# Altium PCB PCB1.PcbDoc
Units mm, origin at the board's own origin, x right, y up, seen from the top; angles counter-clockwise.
Board outline 40.13 x 100 mm, 2 copper layers (Top Layer, Bottom Layer); 44 components, 30 nets, 164 pads, 32 vias.
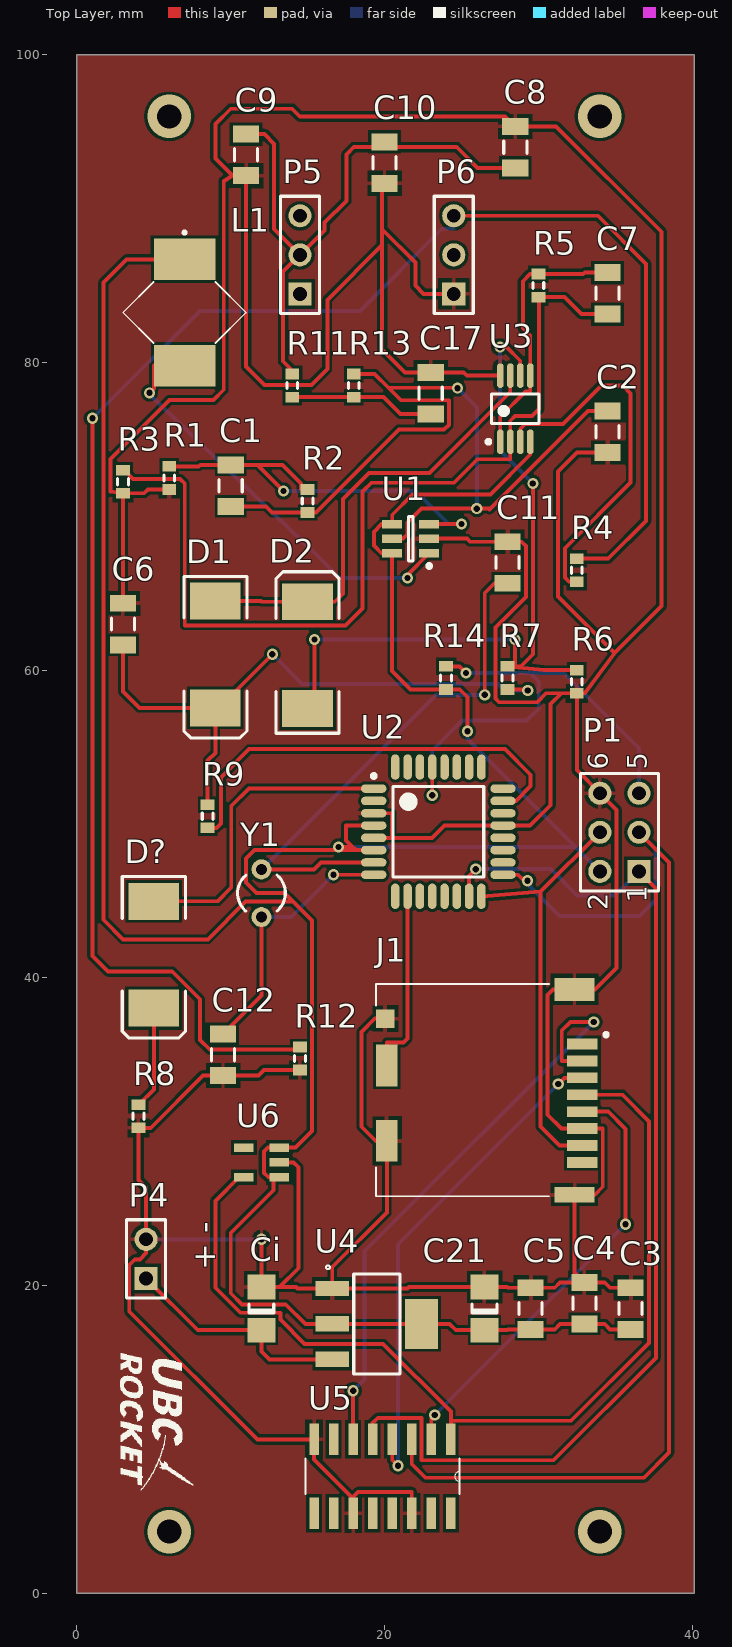
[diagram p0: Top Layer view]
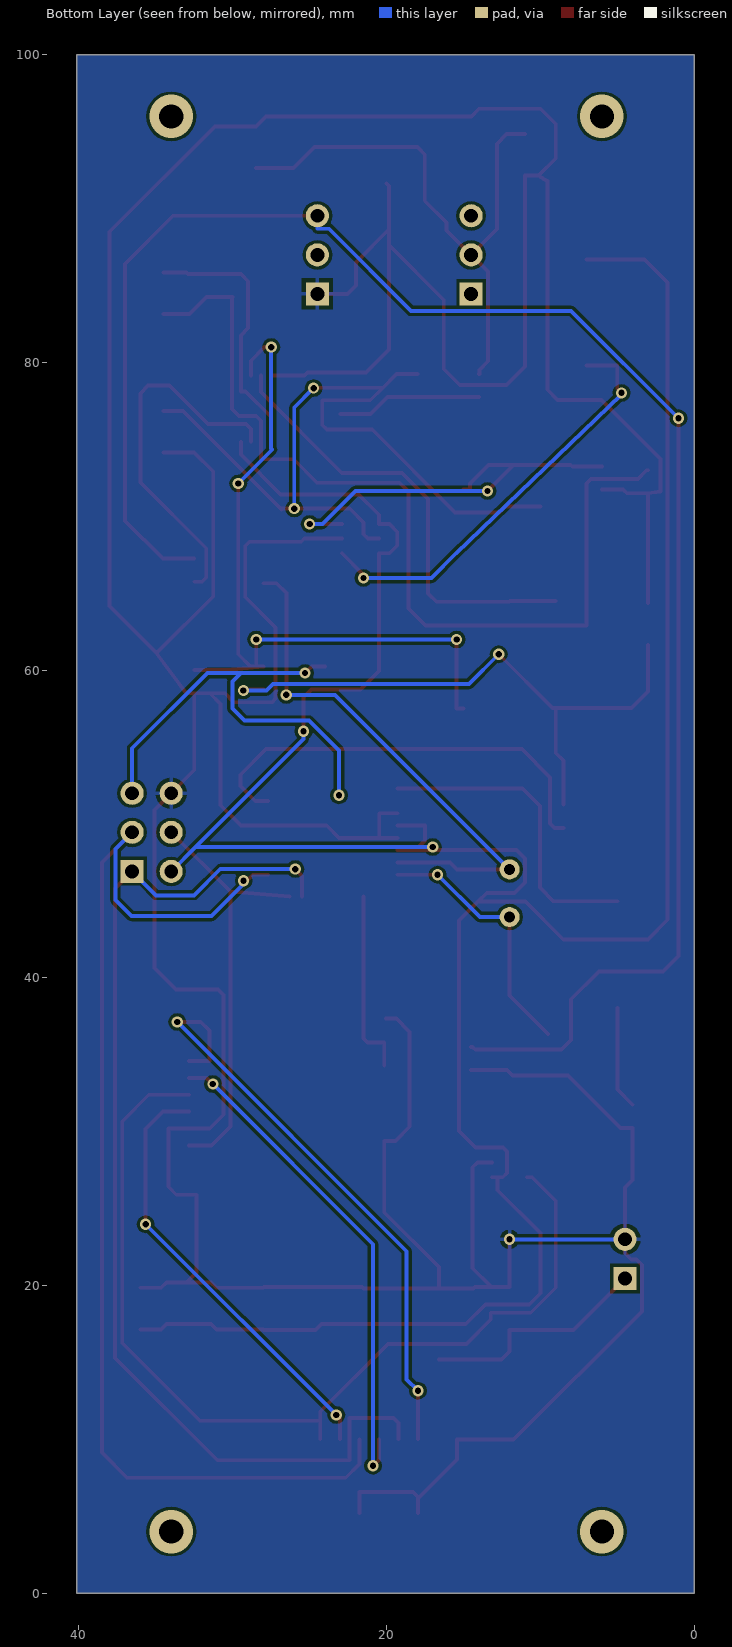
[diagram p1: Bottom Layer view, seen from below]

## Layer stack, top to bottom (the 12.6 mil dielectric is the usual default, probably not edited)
Top Solder: solder mask 0.0102, Solder Resist, Dk 3.5
Top Layer: signal copper 0.0356
Dielectric 1: dielectric 0.32, FR-4, Dk 4.8
Bottom Layer: signal copper 0.0356
Bottom Solder: solder mask 0.0102, Solder Resist, Dk 3.5

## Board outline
0,0 40.132,0 40.132,100 0,100

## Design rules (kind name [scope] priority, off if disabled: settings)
Clearance [All] p1: gap=0.2 ignorepadtopadclearanceinfootprint=FALSE
PolygonConnect [All] p1: connectstyle=Relief reliefconductorwidth=0.254 reliefentries=4 polygonreliefangle="90 Angle" airgapwidth=0.254
RoutingVias [All] p1: holewidth=0.406 width=0.725 viastyle="Through Hole" minholewidth=0.406 minwidth=0.725 maxholewidth=0.406 maxwidth=0.725
SolderMaskExpansion [All] p1: expansion=0.102
Width [All] p1: maxlimit=0.254 minlimit=0.254 preferedwidth=0.254
30 further rules are at their usual default settings.

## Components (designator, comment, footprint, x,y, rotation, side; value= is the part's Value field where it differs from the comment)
C1 "Cap Semi" C1206 10,72 r270 top value=22pF
C2 "Cap Semi" C1206 34.5,75.5 r90 top value=0.47uF
C3 "Cap Semi" C1206 36,18.5 r270 top value=1uF
C4 "Cap Semi" C1206 33,18.85 r270 top value=0.1uF
C5 "Cap Semi" C1206 29.5,18.5 r270 top value=10uF
C6 "Cap Semi" C1206 3,63 r270 top value=10nF
C7 "Cap Semi" C1206 34.5,84.5 r90 top value=5pF
C8 "Cap Semi" C1206 28.5,94 r270 top value=10nF
C9 "Cap Semi" C1206 11,93.5 r90 top value=10nF
C10 "Cap Semi" C1206 20,93 r90 top value=10nF
C11 "Cap Semi" C1206 28,67 r270 top value=22pF
C12 "Cap Semi" C1206 9.5,35 r90 top value=22pF
C17 "Cap Semi" C1206 23,78 r270 top value=10nF
C21 "47uF 6.3V" 1206 26.5,18.5 r90 top value=100pF
Ci "47uF 6.3V" 1206 12,18.5 r90 top value=100pF (schematic designator C?)
D1 "Diode" SMC 9,61.025 r270 top
D2 "Diode" SMC 15,60.975 r90 top
D? "Diode" SMC 5,41.5 r270 top
J1 "DM3CS-SF" HRS_DM3CS-SF_DM3CS-SF(Primary) 26.5,32.5 r90 top
L1 "CDR7D28MNNP-101NC" CDR7D28MNNP101NC 7,83.5 r270 top
P1 "ICSP Header" HDR2X3 36.54,46.92 r90 top
P4 "Header 2" HDR1X2 4.5,20.46 r90 top
P5 "Header 3" HDR1X3 14.5,84.46 r90 top
P6 "Header 3" HDR1X3 24.5,84.46 r90 top
R1 "Res3" J1-0603 6,72.5 r90 top value=10K
R2 "Res3" J1-0603 15,71 r270 top value=226K
R3 "Res3" J1-0603 3,72.25 r90 top value=500
R4 "Res3" J1-0603 32.5,66.5 r270 top value=1K
R5 "Res3" J1-0603 30,85 r90 top value=10K
R6 "Res3" J1-0603 32.5,59.25 r90 top value=100K
R7 "Res3" J1-0603 28,59.5 r90 top value=100K
R8 "Res3" J1-0603 4,31 r90 top value=1K
R9 "Res3" J1-0603 8.5,50.5 r270 top value=1K
R11 "Res3" J1-0603 14,78.5 r90 top value=49.9
R12 "Res3" J1-0603 14.5,34.75 r90 top value=49.9
R13 "Res3" J1-0603 18,78.5 r270 top value=49.9
R14 "Res3" J1-0603 24,59.5 r90 top value=10K
U1 "LT3461AES6" LT-S6-6-TSOT-23_N 21.7,68.55 r180 top
U2 "ATmega328P-15AZ" 32MA_N 23.5,49.5 r0 top
U3 "LT1807CMS8" LT-MS8-8_N 28.5,77 r90 top
U4 "NCP1117ST50T3G" SOT230P700X180-4N 19.5,17.5 r0 top
U5 "CD74HC4050M" SOIC127P600X175-16N 15.42,5.199 r270 top
U6 "LP2985IM5-3.3" SOT95P285X120-5N 12,28 r180 top
Y1 "XTAL" R38 12,45.5 r180 top

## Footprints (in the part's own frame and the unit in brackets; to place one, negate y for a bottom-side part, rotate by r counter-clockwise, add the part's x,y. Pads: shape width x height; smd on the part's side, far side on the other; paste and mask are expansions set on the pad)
32MA_N [mm] "Thin QFP, 32-Leads, Body 7x7mm, Pitch 0.8mm, IPC Medium Density"
  oval 1.65x0.55 smd: 1(-4.2,2.8) 2(-4.2,2) 3(-4.2,1.2) 4(-4.2,0.4) 5(-4.2,-0.4) 6(-4.2,-1.2) 7(-4.2,-2) 8(-4.2,-2.8) 17(4.2,-2.8) 18(4.2,-2) 19(4.2,-1.2) 20(4.2,-0.4) 21(4.2,0.4) 22(4.2,1.2) 23(4.2,2) 24(4.2,2.8)
  oval 0.55x1.65 smd: 9(-2.8,-4.2) 10(-2,-4.2) 11(-1.2,-4.2) 12(-0.4,-4.2) 13(0.4,-4.2) 14(1.2,-4.2) 15(2,-4.2) 16(2.8,-4.2) 25(2.8,4.2) 26(2,4.2) 27(1.2,4.2) 28(0.4,4.2) 29(-0.4,4.2) 30(-1.2,4.2) 31(-2,4.2) 32(-2.8,4.2)
  silkscreen extent -4.32,-2.95 2.95,3.75, body extent -3.5,-3.5 3.5,3.5, height 1.2
1206 [mm] "Chip Capacitor; Body 3.2 x 1.6 mm (LxW typ)"
  rect 1.6x1.8 smd: 1(-1.4,0) 2(1.4,0)
  silkscreen extent -0.3,-0.8 0.3,0.8
C1206 [mm] "Chip Capacitor, Body 3.2x1.6mm, IPC High Density"
  rect 1.1x1.7 smd: 1(-1.35,0) 2(1.35,0)
  silkscreen extent -0.4,-0.75 0.4,0.75, body extent -1.7,-0.9 1.7,0.9, height 1.3
CDR7D28MNNP101NC [mm]
  rect 2.7x4 smd: 1(-3.2,0) 2(3.7,0)
  silkscreen extent -5.05,-4 2.25,4
HDR1X2 [mm] "Connector; Header; 2 Position"
  rect 1.5x1.5 hole 0.9: 1(0,0)
  round 1.5 hole 0.9: 2(2.54,0)
  silkscreen extent -1.27,-1.27 3.81,1.27
HDR1X3 [mm] "Connector; Header; 3 Position"
  rect 1.5x1.5 hole 0.9: 1(0,0)
  round 1.5 hole 0.9: 2(2.54,0) 3(5.08,0)
  silkscreen extent -1.27,-1.27 6.35,1.27
HDR2X3 [mm] "Connector; Header; 3x2 Position"
  rect 1.5x1.5 hole 0.9: 1(0,0)
  round 1.5 hole 0.9: 2(0,2.54) 3(2.54,0) 4(2.54,2.54) 5(5.08,0) 6(5.08,2.54)
  silkscreen extent -1.27,-1.27 6.35,3.81
HRS_DM3CS-SF_DM3CS-SF(Primary) [mm]
  rect 0.7x2 smd: 1(3.2,-6.35) 2(2.1,-6.35) 3(1,-6.35) 4(-0.1,-6.35) 5(-1.2,-6.35) 6(-2.3,-6.35) 7(-3.4,-6.35) 8(-4.5,-6.35)
  rect 2.7x1.4 smd: 9(1.8,6.35) S3(-3.1,6.35)
  rect 1x2.6 smd: S1(-6.6,-5.85)
  rect 1.5x2.6 smd: S2(6.75,-5.85)
  rect 1.2x1.2 smd: S5(4.85,6.45)
  silkscreen extent -6.7,-8.02 7.1,7.05
J1-0603 [mm] "Chip Resistor, Body 1.6x0.8mm, IPC High Density"
  rect 0.7x0.9 smd: 1(-0.75,0) 2(0.75,0)
  silkscreen extent -0.2,-0.35 0.2,0.35, body extent -0.85,-0.48 0.85,0.48, height 0.9
LT-MS8-8_N [mm] "SOP, 8-Leads, Body 3x3mm, Pitch 0.65mm, IPC Medium Density"
  oval 1.6x0.45 smd: 1(-2.15,0.975) 2(-2.15,0.325) 3(-2.15,-0.325) 4(-2.15,-0.975) 5(2.15,-0.975) 6(2.15,-0.325) 7(2.15,0.325) 8(2.15,0.975)
  silkscreen extent -2.27,-1.55 0.95,1.87, body extent -1.55,-1.55 1.55,1.55, height 1.1
LT-S6-6-TSOT-23_N [mm] "SOT23, 6-Leads, Body 2.9x1.75mm, Pitch 0.95mm, IPC Medium Density"
  rect 1.3x0.55 smd: 1(-1.2,0.95) 2(-1.2,0) 3(-1.2,-0.95) 4(1.2,-0.95) 5(1.2,0) 6(1.2,0.95)
  silkscreen extent -1.33,-1.45 0.15,1.9, body extent -0.87,-1.45 0.87,1.45, height 1
R38 [mm] "Crystal, Thru-Hole; 2 Leads; Body 3.1 x 8.2 mm (Dia.xH)"
  round 1.3 hole 0.7: 1(0,1.55) 2(0,-1.55)
  silkscreen extent -1.55,-1.19 1.55,1.17
SMC [mm] "DO-214-AB/SMC; 2 C-Bend Leads; Body 7.9 x 5.9 mm, inc. leads (LxW)"
  rect 2.4x3.3 smd: 1(-3.475,0) 2(3.475,0)
  silkscreen extent -5.07,-2.05 5.43,2.05
SOIC127P600X175-16N [mil]
  rect 81x24 smd: 1(-189,350) 2(-189,300) 3(-189,250) 4(-189,200) 5(-189,150) 6(-189,100) 7(-189,50) 8(-189,0) 9(0,0) 10(0,50) 11(0,100) 12(0,150) 13(0,200) 14(0,250) 15(0,300) 16(0,350)
  silkscreen extent -140,-22 -49,372
SOT95P285X120-5N [mil]
  rect 50x22 smd: 1(-45,38) 2(-45,0) 3(-45,-38) 4(45,-38) 5(45,38)
SOT230P700X180-4N [mm]
  rect 2.15x1 smd: 1(-2.9,2.3) 2(-2.9,0) 3(-2.9,-2.3)
  rect 2.15x3.25 smd: 4(2.9,0)
  silkscreen extent -3.3,-3.25 1.5,3.81

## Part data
C1 C2 C3 C4 C5 C6 C7 C8 C9 C10 C11 C12 C17: "Capacitor (Semiconductor SIM Model)"
C21 Ci: library part C1206, "Ceramic Chip Capacitor - Standard", PackageDocument=Mar-2001
D1 D2 D?: "Default Diode"
J1: "Conn Micro SD Card HDR 8 POS 1.1mm Solder RA SMD Embossed T/R 0.5A", Package=None
L1: "Fixed Inductors 100uH .65A", Manufacturer_Name=Sumida
P1: library part "Header 3X2", "Header, 3-Pin, Dual row"
P4: "Header, 2-Pin"
P5 P6: "Header, 3-Pin"
R1 R2 R3 R4 R5 R6 R7 R8 R9 R11 R12 R13 R14: "Resistor"
U1: "3 MHz Step-Up DC/DC Converter with Integrated Schottky, 6-pin SOT23 (S6-6), -40 to 85 degC", Manufacturer="Linear Technology", Supplier Part Number 1=24W8904
U2: "8-bit Automotive AVR Microcontroller, 32KB Flash, 1KB EEPROM, 2KB SRAM, 23 GPIO pins, Automotive Grade (-40°C to +125°C), 32-Pin TQFP", Supplier Part Number 1=ATMEGA328P-15AZ-ND
U3: "Dual Channel, High Speed, Low Noise Precision Operational Amplifier, 325 MHz Typical GBW, 125 V/us Typical SR, 2.5 to 12.6 V, 8-Pin SOP (MS8-8), Commercial", Linear Technology Part Number=LT1807, Manufacturer="Linear Technology", Supplier Part Number 1=LT1807CMS8-ND
U4: Package="TO-261-4 HTC Korea"
U5: Package="SOIC-16 Harris"
U6: "Micropower 150 mA Low-Noise Ultra Low-Dropout Regulator in SOT-23 and micro SMD Packages 5-SOT-23 -40 to 125", Package="SOT-23 Texas Instruments"
Y1: "Crystal Oscillator"

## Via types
v1: diameter 0.725, hole 0.406, Top Layer to Bottom Layer, 28 vias
v2: diameter 2.82, hole 1.58, Top Layer to Bottom Layer, 4 vias

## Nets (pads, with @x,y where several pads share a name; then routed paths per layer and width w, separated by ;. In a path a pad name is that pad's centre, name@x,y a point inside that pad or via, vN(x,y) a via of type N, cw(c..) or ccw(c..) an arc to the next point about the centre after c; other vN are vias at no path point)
+3.3: J1.4 U5.1 U6.5 | length 63.3
  Top Layer w0.254: U6.5 10.535,27.035 9,25.5 9,19.854 10.627,18.227 13.227,18.227 13.227,17.78 14.802,16.205 19.914,16.205 24.31,11.809 24.31,11.204 ; U5.1 24.31,11.204 ; J1.4 35.458,32.4 37.186,30.673 37.186,16.256 32.133,11.204 24.31,11.204
+5: C3.2 C4.2 C5.2 C21.1 L1.1 P1.2 R14.1 U1.4 U1.6 U2.4 U2.6 U3.4 U4.2 U4.4 U6.1 U6.3 | length 196.2
  Top Layer w0.254: L1.1 3.236,86.7 1.727,85.192 1.727,43.773 3,42.5 8.515,42.5 10.973,44.958 14.046,44.958 ; U6.1 U6.1@12.776,27.035 ; v1(17,48.5) 17.715,48.5 17.825,48.61 ; U2.6 18.136,48.3 ; U2.4 17.5,49.9 17.5,48.936 17.825,48.61 ; U1.6 U1.6@20.498,67.6 ; v1(25.4,56.028) 25.4,58.242 24.892,58.75 R14.1 21.692,58.75 20.498,59.944 U1.6@20.498,67.6 ; U3.4 29.475,74.016 26.884,71.425 21.821,71.425 20.5,70.104 U1.4 19.812,69.5 19.304,68.992 19.304,68.108 19.812,67.6 U1.6@20.498,67.6 ; C3.2 34.665,17.15 34.315,17.5 C4.2 31.414,17.5 31.064,17.15 C5.2 28.015,17.15 27.965,17.1 C21.1 24.632,17.1 24.232,17.5 U4.4 U4.2 14.851,17.5 13.581,18.771 10.726,18.771 10,19.496 10,23.411 12.776,26.187 U6.1@12.776,27.035 ; U6.1@12.776,27.035 12.446,27.035 12.167,27.314 12.167,28.702 12.43,28.965 U6.3 14.224,28.965 15.291,30.032 15.291,43.713 14.046,44.958 ; 14.046,44.958 13.487,45.517 11.684,45.517 10.998,46.203 10.998,47.752 11.546,48.3 18.136,48.3 ; 17.825,48.61 18.136,48.3
  Bottom Layer w0.254: v1(17,48.5) 32.341,48.5 32.381,48.539 ; v1(25.4,56.028) 25.4,55.52 32.381,48.539 ; P1.2 32.381,48.539
A0: R9.2 U2.23 | length 28.5
  Top Layer w0.254: R9.2 9.085,49.75 9.373,50.038 9.373,53.035 11.201,54.864 27.838,54.864 29.5,53.202 29.5,52.462 28.538,51.5 U2.23
BATT: Ci.1 P4.1 U4.3 | length 15.1
  Top Layer w0.254: P4.1 7.86,17.1 Ci.1 12,15.717 12.517,15.2 U4.3
CD: J1.9 U2.10 | length 12.2
  Top Layer w0.254: J1.9 20.15,35.789 21.234,35.789 21.5,36.054 U2.10
CS: U5.7
D3: D?.1 U2.1 | length 20.4
  Top Layer w0.254: D?.1 9.144,44.975 10.033,45.864 10.033,51.157 11.176,52.3 U2.1
FB: C1.1 R1.2 R2.1 U1.3 | length 26.9
  Top Layer w0.254: R1.2 7.925,73.25 8.025,73.35 C1.1 11.74,73.35 ; v1(13.437,71.653) 11.74,73.35 ; R2.1 14.58,71.75 14.58,72.136 13.366,73.35 11.74,73.35 ; U1.3 v1(25,69.5)
  Bottom Layer w0.254: v1(13.437,71.653) 22.022,71.653 24.175,69.5 v1(25,69.5)
GND: C2.1 C3.1 C4.1 C5.1 C6.1 C8.1 C9.1 C10.1 C11.1 C12.1 C17.1 C21.2 Ci.2 J1.6 J1.S1 J1.S2 J1.S3 J1.S5 P1.6 P4.2 P6.1 R1.1 R3.1 R6.1 R8.1 R12.1 U1.2 U2.3 U2.5 U2.21 U3.8 U4.1 U5.8 U5.11 U5.14 U6.2 | length 388.9
  Top Layer w0.254: C6.1 R3.1 ; R1.1 4.619,71.75 4.369,71.5 R3.1 ; C9.1 C9.1@10.998,92.15 ; v1(12,23) Ci.2 13.183,19.9 ; U6.2 14.088,28 14.402,27.686 14.402,21.119 13.183,19.9 ; R12.1 12.161,34 11.811,33.65 C12.1 8.201,33.65 4.801,30.25 R8.1 4,26.865 4.5,26.365 P4.2 4.5,22.098 4.094,21.692 3.759,21.692 3.404,21.336 3.404,18.313 11.735,9.982 U5.8@15.42,9.982 ; U5.8 U5.8@15.42,9.982 ; U5.11 U5.11@17.96,6.147 ; U2.5 20.472,49.1 ; U2.3 20.472,50.7 20.472,49.1 ; C10.1 19.837,91.487 19.837,88.663 ; J1.S5 19.367,37.35 18.5,36.483 18.5,30.319 19.431,29.388 J1.S3@20.15,29.388 ; J1.S3 J1.S3@20.15,29.388 ; U5.14 21.77,6.579 18.288,6.579 17.96,6.251 U5.11@17.96,6.147 ; U1.2 25.349,68.55 25.549,68.35 C11.1 28.907,68.35 29.185,68.072 29.185,64.745 27.207,62.767 27.207,58.162 27.457,57.912 29.917,57.912 30.505,58.5 31.496,58.5 ; P6.1 22.54,84.46 22,85 22,86.5 19.837,88.663 ; U3.8 25.346,79.15 25.146,79.35 C17.1 21.336,79.35 19.837,80.849 19.837,87.63 ; C2.1 32.512,74.15 31.269,72.907 31.269,64.794 34.95,61.112 ; C3.1 34.665,19.85 34.315,20.2 C4.1 ; R3.1 2.184,71.627 2.184,73.739 6.017,77.572 8.89,77.572 9.55,78.232 9.55,91.794 10.11,92.15 ; 10.11,92.15 9,93.26 9,95.5 10,96.5 13.99,96.5 14.49,96 27.85,96 C8.1 31.15,95.35 38,88.5 38,64.162 34.95,61.112 ; 10.11,92.15 C9.1@10.998,92.15 ; C9.1@10.998,92.15 10.998,79.731 12.192,78.537 15.24,78.537 16.281,79.578 16.281,84.074 19.837,87.63 ; 13.183,19.9 14.249,19.9 14.349,19.8 U4.1 ; U5.8@15.42,9.982 15.42,8.687 U5.11@17.96,6.147 ; U4.1 16.6,21.19 20.15,24.74 J1.S3@20.15,29.388 ; U4.1 21.488,19.8 21.588,19.9 C21.2 27.965,19.9 28.015,19.85 C5.1 31.064,19.85 31.414,20.2 C4.1 ; 19.837,87.63 19.837,88.663 ; 20.472,49.1 23.089,49.1 23.889,49.9 U2.21 29.464,49.9 30.785,51.221 30.785,57.789 31.496,58.5 ; 31.496,58.5 R6.1 ; R6.1 33.02,58.5 34.95,61.112 ; R6.1 32.5,53.5 P1.6 35.077,50.923 35.077,40.64 33.687,39.25 J1.S2 30.963,39.25 30.598,38.885 30.598,31.098 31.496,30.2 J1.6 34.188,30.2 34.188,26.416 33.672,25.9 J1.S1 32.35,20.85 C4.1
  Bottom Layer w0.254: P4.2 v1(12,23)
MISO: J1.7 P1.4 U2.16 | length 27.8
  Top Layer w0.254: U2.16 26.3,45.288 30.144,45.604 ; J1.7 31.377,29.1 30.144,30.333 30.144,45.604 ; P1.4 30.144,45.604
MOSI: P1.1 U2.15 U5.5 | length 71.1
  Top Layer w0.254: U5.5 19.23,11.051 19.558,11.379 22.403,11.379 22.403,8.636 30.988,8.636 37.643,15.291 37.643,45.817 P1.1 ; U2.15 25.5,46.633 v1(25.933,47.066)
  Bottom Layer w0.254: v1(25.933,47.066) 30.81,47.066 32.512,45.364 34.984,45.364 P1.1
NetC6_2: C6.2 D1.2 R7.1 R9.1 | length 40.1
  Top Layer w0.254: C6.2 2.997,61.65 2.997,58.617 4.064,57.55 D1.2 ; R9.1 8.5,54.127 9,54.627 D1.2 ; v1(12.706,61.036) 9.22,57.55 D1.2 ; R7.1 29.236,58.75 v1(29.312,58.674)
  Bottom Layer w0.254: v1(12.706,61.036) 14.638,59.104 27.37,59.104 27.801,58.674 v1(29.312,58.674)
NetC7_1: C7.1 R3.2 R5.1 U3.2 | length 60.6
  Top Layer w0.254: R3.2 3.099,73 3.658,72.441 6.706,72.441 7.01,72.136 7.01,62.916 17.475,62.916 18.567,64.008 18.567,71.603 19.152,72.187 24.511,72.187 26.035,73.711 28.175,73.711 U3.2 28.175,76.218 28.47,76.513 29.594,76.513 30.048,76.967 R5.1@30.048,84.25 ; R5.1 R5.1@30.048,84.25 ; C7.1 32.799,83.15 31.699,84.25 R5.1@30.048,84.25
NetC7_2: C7.2 R5.2 U3.1 U3.5 | length 17.4
  Top Layer w0.254: U3.1 27.525,76.477 29.168,78.12 29.475,78.12 U3.5 29.475,81.763 29,82.238 29,85.286 29.464,85.75 R5.2 32.918,85.75 33.018,85.85 C7.2
NetC8_2: C8.2 C9.2 C10.2 P5.2 R11.2 | length 38
  Top Layer w0.254: C9.2 12.192,94.85 12.827,94.215 12.827,88.673 P5.2 ; R11.2 13.97,79.25 13.97,79.527 13.411,80.086 13.411,85.911 P5.2 ; C8.2 26.042,92.65 24.692,94 18,94 17.515,93.515 17.515,90.515 16.094,89.094 16.094,88.594 P5.2
NetC11_2: C11.2 U2.7 Y1.2 | length 35.1
  Top Layer w0.254: Y1.2 15.418,47.05 15.868,47.5 U2.7 ; v1(26.518,58.395) 26.518,65.024 27.144,65.65 C11.2
  Bottom Layer w0.254: Y1.2 23.345,58.395 v1(26.518,58.395)
NetC12_2: C12.2 U2.8 Y1.1 | length 17.1
  Top Layer w0.254: C12.2 12,38.85 Y1.1 ; v1(16.688,46.7) U2.8
  Bottom Layer w0.254: Y1.1 13.938,43.95 v1(16.688,46.7)
NetC17_2: C17.2 R11.1 R13.2 | length 9.5
  Top Layer w0.254: R11.1 R13.2 19.939,77.75 21.039,76.65 C17.2
NetD1_1: D1.1 D2.2 U3.7 | length 29.5
  Top Layer w0.254: D1.1 11.963,64.5 12.013,64.45 D2.2 16.764,64.45 17.297,64.983 17.297,71.12 18.999,72.822 22.915,72.822 28.175,78.082 U3.7
NetD2_1: D2.1 R6.2 R7.2 U3.6 | length 49.8
  Top Layer w0.254: D2.1 15.443,57.5 v1(15.443,62.001) ; v1(27.5,81) 27.941,81 28.825,80.116 U3.6 ; v1(28.473,62.001) 28.473,60.25 ; v1(29.642,72.136) 29.642,61.037 28.854,60.25 28.473,60.25 ; R6.2 30.374,60 R7.2 28.473,60.25
  Bottom Layer w0.254: v1(15.443,62.001) v1(28.473,62.001) ; v1(27.5,81) 27.5,74.414 27.432,74.346 v1(29.642,72.136)
NetD?_2: D?.2 R8.2 | length 6.7
  Top Layer w0.254: R8.2 5,32.75 D?.2
NetP6_3: P6.3 R4.1 R12.2 | length 118
  Top Layer w0.254: v1(1.016,76.378) 1.016,41.427 2.032,40.411 6.198,40.411 8.001,38.608 8.001,35.966 8.636,35.331 14.233,35.331 14.402,35.5 R12.2 ; P6.3 33.879,89.54 37,86.419 37,69.706 34.544,67.25 R4.1
  Bottom Layer w0.254: v1(1.016,76.378) 8.001,83.363 18.415,83.363 23.749,88.697 24.5,88.697 P6.3
NetR4_2: R4.2 U3.3 | length 24
  Top Layer w0.254: U3.3 28.825,75.692 29.13,75.997 31.598,75.997 34.101,78.5 35.5,78.5 36,78 36,72.205 31.723,67.928 31.723,66.031 32.004,65.75 R4.2
RESET: P1.5 R14.2 U2.29 | length 33
  Top Layer w0.254: v1(23.1,51.867) U2.29 ; R14.2 24.865,60.25 v1(25.298,59.817)
  Bottom Layer w0.254: v1(23.1,51.867) 23.1,54.777 25.04,56.717 29.235,56.717 30.023,57.506 30.023,59.258 29.464,59.817 ; v1(25.298,59.817) 29.464,59.817 ; P1.5 36.54,54.925 31.648,59.817 29.464,59.817
SCK: P1.3 U2.17 U5.3 | length 77
  Top Layer w0.254: U5.3 21.77,8.382 22.652,7.5 36.862,7.5 38.506,9.144 38.506,47.494 P1.3 ; U2.17 28.687,46.7 29.073,46.314 v1(29.295,46.314)
  Bottom Layer w0.254: v1(29.295,46.314) 29.295,46.092 31.369,44.018 36.576,44.018 37.617,45.06 37.617,48.383 P1.3
SDCK: J1.5 U5.2 | length 28.7
  Top Layer w0.254: U5.2 23.04,11.356 v1(23.266,11.582) ; J1.5 34.544,31.3 35.662,30.182 v1(35.662,23.978)
  Bottom Layer w0.254: v1(23.266,11.582) v1(35.662,23.978)
SDCS: J1.2 U5.6 | length 39.2
  Top Layer w0.254: U5.6 v1(17.96,13.159) ; J1.2 31.521,34.6 31.521,36.576 32.08,37.135 v1(33.604,37.135)
  Bottom Layer w0.254: v1(17.96,13.159) 18.694,13.894 18.694,22.225 v1(33.604,37.135)
SDMOSI: J1.3 U5.4 | length 32.7
  Top Layer w0.254: U5.4 20.5,8.659 v1(20.879,8.28) ; v1(31.293,33.096) 31.697,33.5 J1.3
  Bottom Layer w0.254: v1(20.879,8.28) 20.879,22.682 v1(31.293,33.096)
SW: L1.2 U1.1 | length 27.8
  Top Layer w0.254: v1(4.724,78.029) 5.004,78.308 5.004,79.8 L1.2 ; v1(21.5,66) 21.5,66.2 U1.1
  Bottom Layer w0.254: v1(4.724,78.029) 4.724,77.927 15.483,67.6 17.083,66 v1(21.5,66)
VOUT: C1.2 C2.2 R2.2 R13.1 U1.5 | length 56
  Top Layer w0.254: C1.2 12.294,70.65 12.694,70.25 R2.2 15.538,70.25 20.93,75.641 23.876,75.641 24.181,75.946 24.181,77.546 21.059,77.546 20.245,78.36 ; R13.1 19.355,79.25 20.245,78.36 ; U1.5 21.204,68.55 21.488,68.834 21.488,69.596 22.392,70.5 v1(26,70.5) 26.757,70.5 26.822,70.434 33.238,76.85 C2.2 ; v1(24.74,78.334) 20.245,78.36
  Bottom Layer w0.254: v1(24.74,78.334) 26,77.073 v1(26,70.5)
pads on no net: J1.1 J1.8 P5.1 P5.3 P6.2 U2.2 U2.9 U2.11 U2.12 U2.13 U2.14 U2.18 U2.19 U2.20 U2.22 U2.24 U2.25 U2.26 U2.27 U2.28 U2.30 U2.31 U2.32 U5.9 U5.10 U5.12 U5.13 U5.15 U5.16 U6.4
copper on no net:
  other v2: 6,4 34,4 6,96 34,96

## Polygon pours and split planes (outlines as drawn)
GND on Bottom Layer "bottom" (solid, pour order 6): 0,0 40.132,0 40.132,100 0,100
GND on Top Layer "Top Layer-No Net" (solid, pour order 7): 0,0 40.132,0 40.132,100 0,100

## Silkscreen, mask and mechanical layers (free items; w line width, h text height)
Top Overlay:
  drawing of 13 lines, arcs and shapes, not listed
  text "+ -" at 9,21 h1.52 r90
Mechanical 1:
  lines w0.254: 0,0 0,100 40,100 40,0 0,0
